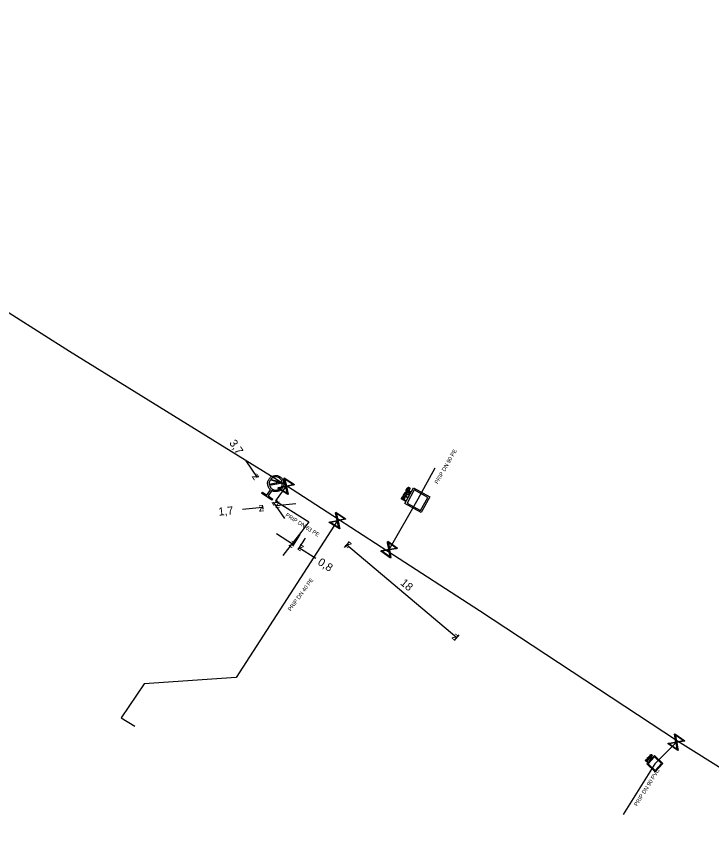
# Model space of a CAD drawing. Extents: x -643544 to -637295, y -1119190 to -1111715.
# Drawn here: x -642792.2 to -642705.4, y -1114896.7 to -1114793.9 of the extents above; entities that cross this region are included whole.
import ezdxf

# ---------------------------------------------------------------- set-up
doc = ezdxf.new("R2010")
doc.units = 0
for name, color, linetype in [('Default', 7, 'Continuous'), ('VP Hydrant', 7, 'Continuous'), ('VP Kótování', 7, 'Continuous'), ('VP Popis přípojky', 7, 'Continuous'), ('VP Přípojka', 7, 'Continuous'), ('VP Řad', 7, 'Continuous'), ('VP Šachta', 7, 'Continuous'), ('VP Šoupě', 7, 'Continuous')]:
    doc.layers.add(name, color=color, linetype=linetype)

msp = doc.modelspace()

# ---------------------------------------------------------------- linework, layer by layer
at = {"layer": 'Default'}
for points in [[(-642760.44, -1114852.98), (-642760.72, -1114852.76), (-642760.78, -1114852.4), (-642760.86, -1114851.99), (-642760.63, -1114851.65), (-642760.39, -1114851.3), (-642759.99, -1114851.23), (-642759.58, -1114851.15), (-642759.24, -1114851.38), (-642758.9, -1114851.62), (-642758.82, -1114852.02), (-642758.74, -1114852.43), (-642758.97, -1114852.77), (-642759.21, -1114853.11), (-642759.61, -1114853.19), (-642759.97, -1114853.26), (-642760.29, -1114853.09)], [(-642759.02, -1114851.97), (-642759.1, -1114851.7), (-642759.34, -1114851.54), (-642759.62, -1114851.35), (-642759.95, -1114851.41), (-642760.28, -1114851.48), (-642760.47, -1114851.76), (-642760.63, -1114851.99), (-642760.61, -1114852.27)], [(-642760.58, -1114852.45), (-642760.5, -1114852.72), (-642760.26, -1114852.88), (-642759.98, -1114853.07), (-642759.65, -1114853.01), (-642759.32, -1114852.95), (-642759.13, -1114852.67), (-642758.96, -1114852.43), (-642758.99, -1114852.15)], [(-642743.76, -1114853.45), (-642743.72, -1114853.39), (-642743.69, -1114853.36), (-642743.66, -1114853.33), (-642743.61, -1114853.33), (-642743.57, -1114853.33), (-642743.52, -1114853.35), (-642743.47, -1114853.38), (-642743.45, -1114853.44), (-642743.44, -1114853.49), (-642743.46, -1114853.57), (-642743.44, -1114853.55), (-642743.42, -1114853.54), (-642743.38, -1114853.53), (-642743.32, -1114853.52)], [(-642743.54, -1114853.59), (-642743.52, -1114853.54), (-642743.51, -1114853.51), (-642743.51, -1114853.48), (-642743.52, -1114853.46), (-642743.54, -1114853.43), (-642743.56, -1114853.42), (-642743.6, -1114853.4), (-642743.63, -1114853.41), (-642743.67, -1114853.43), (-642743.7, -1114853.48)], [(-642743.32, -1114853.6), (-642743.38, -1114853.61), (-642743.42, -1114853.61), (-642743.45, -1114853.62), (-642743.47, -1114853.63), (-642743.49, -1114853.64), (-642743.5, -1114853.65), (-642743.51, -1114853.66), (-642743.52, -1114853.69)], [(-642743.4, -1114852.81), (-642743.38, -1114852.76), (-642743.36, -1114852.74), (-642743.33, -1114852.71), (-642743.3, -1114852.69), (-642743.27, -1114852.67), (-642743.23, -1114852.68), (-642743.19, -1114852.68), (-642743.15, -1114852.7), (-642743.09, -1114852.74), (-642743.07, -1114852.8), (-642743.04, -1114852.86), (-642743.1, -1114852.97)], [(-642743.16, -1114852.94), (-642743.13, -1114852.87), (-642743.13, -1114852.83), (-642743.14, -1114852.79), (-642743.19, -1114852.77), (-642743.22, -1114852.75), (-642743.25, -1114852.76), (-642743.28, -1114852.76), (-642743.3, -1114852.78), (-642743.32, -1114852.79), (-642743.34, -1114852.84)], [(-642744.02, -1114853.94), (-642744, -1114853.89), (-642743.98, -1114853.86), (-642743.95, -1114853.83), (-642743.92, -1114853.81), (-642743.89, -1114853.8), (-642743.85, -1114853.8), (-642743.81, -1114853.8), (-642743.77, -1114853.82), (-642743.71, -1114853.86), (-642743.69, -1114853.92), (-642743.66, -1114853.99), (-642743.72, -1114854.09)], [(-642743.78, -1114854.06), (-642743.75, -1114854), (-642743.76, -1114853.96), (-642743.76, -1114853.92), (-642743.81, -1114853.89), (-642743.84, -1114853.88), (-642743.87, -1114853.88), (-642743.9, -1114853.88), (-642743.92, -1114853.9), (-642743.94, -1114853.92), (-642743.96, -1114853.96)], [(-642713.35, -1114886.44), (-642713.32, -1114886.41), (-642713.3, -1114886.4), (-642713.27, -1114886.39), (-642713.24, -1114886.39), (-642713.22, -1114886.4), (-642713.19, -1114886.42), (-642713.17, -1114886.44), (-642713.16, -1114886.48), (-642713.16, -1114886.51), (-642713.19, -1114886.56), (-642713.17, -1114886.55), (-642713.16, -1114886.55), (-642713.13, -1114886.55), (-642713.1, -1114886.55)], [(-642713.24, -1114886.56), (-642713.22, -1114886.53), (-642713.21, -1114886.52), (-642713.21, -1114886.5), (-642713.21, -1114886.48), (-642713.21, -1114886.47), (-642713.23, -1114886.45), (-642713.25, -1114886.44), (-642713.27, -1114886.44), (-642713.29, -1114886.44), (-642713.32, -1114886.47)], [(-642713.04, -1114886.11), (-642713.01, -1114886.08), (-642713, -1114886.07), (-642712.98, -1114886.06), (-642712.96, -1114886.05), (-642712.93, -1114886.05), (-642712.91, -1114886.05), (-642712.89, -1114886.06), (-642712.87, -1114886.08), (-642712.83, -1114886.11), (-642712.83, -1114886.15), (-642712.83, -1114886.2), (-642712.88, -1114886.25)], [(-642712.91, -1114886.22), (-642712.88, -1114886.19), (-642712.88, -1114886.16), (-642712.88, -1114886.14), (-642712.9, -1114886.12), (-642712.92, -1114886.1), (-642712.94, -1114886.1), (-642712.96, -1114886.1), (-642712.97, -1114886.11), (-642712.98, -1114886.11), (-642713, -1114886.14)], [(-642713.59, -1114886.69), (-642713.56, -1114886.67), (-642713.55, -1114886.66), (-642713.53, -1114886.64), (-642713.51, -1114886.64), (-642713.48, -1114886.63), (-642713.46, -1114886.64), (-642713.44, -1114886.65), (-642713.42, -1114886.66), (-642713.38, -1114886.7), (-642713.38, -1114886.74), (-642713.38, -1114886.78), (-642713.43, -1114886.84)], [(-642713.46, -1114886.81), (-642713.43, -1114886.77), (-642713.43, -1114886.75), (-642713.43, -1114886.72), (-642713.45, -1114886.7), (-642713.47, -1114886.69), (-642713.49, -1114886.68), (-642713.5, -1114886.68), (-642713.52, -1114886.69), (-642713.53, -1114886.7), (-642713.55, -1114886.72)], [(-642713.11, -1114886.6), (-642713.15, -1114886.59), (-642713.17, -1114886.59), (-642713.19, -1114886.59), (-642713.2, -1114886.59), (-642713.22, -1114886.6), (-642713.23, -1114886.6), (-642713.23, -1114886.61), (-642713.25, -1114886.62)]]:
    msp.add_open_spline(points, degree=3, dxfattribs=at)
at = {"layer": 'VP Hydrant'}
for points in [[(-642760.61, -1114852.27), (-642759.02, -1114851.97)], [(-642758.99, -1114852.15), (-642760.58, -1114852.45)], [(-642760.29, -1114853.09), (-642760.75, -1114853.76), (-642760.18, -1114854.15), (-642760.28, -1114854.3), (-642761.57, -1114853.42), (-642761.47, -1114853.27), (-642760.9, -1114853.66), (-642760.44, -1114852.98)]]:
    msp.add_lwpolyline(points, dxfattribs=at)
at = {"layer": 'VP Kótování'}
for points in [[(-642763.54, -1114849.38), (-642762.14, -1114851.45)], [(-642762.31, -1114851.57), (-642762.34, -1114851.59)], [(-642760.24, -1114854.64), (-642760.27, -1114854.66)], [(-642758.67, -1114856.59), (-642760.07, -1114854.52)], [(-642763.94, -1114855.42), (-642761.45, -1114855.17)], [(-642761.47, -1114855.03), (-642761.43, -1114855.42)], [(-642759.78, -1114854.85), (-642759.74, -1114855.24)], [(-642757.28, -1114854.74), (-642759.76, -1114854.99)], [(-642759.69, -1114858.46), (-642757.58, -1114859.81)], [(-642756.8, -1114858.58), (-642757.72, -1114860.02)], [(-642756.12, -1114859.01), (-642757.04, -1114860.45)], [(-642750.7, -1114859.51), (-642751.28, -1114860.19)], [(-642750.96, -1114859.81), (-642737.21, -1114871.42)], [(-642754.8, -1114861.58), (-642756.91, -1114860.24)], [(-642736.95, -1114871.12), (-642737.53, -1114871.81)]]:
    msp.add_lwpolyline(points, dxfattribs=at)
at = {"layer": 'VP Přípojka'}
for points in [[(-642745.8, -1114860.67), (-642745.65, -1114860.46), (-642742.04, -1114854.13), (-642739.89, -1114850.23)], [(-642758.47, -1114852.47), (-642759.83, -1114854.36), (-642755.69, -1114856.99), (-642756.53, -1114858.15), (-642758.9, -1114861.18)], [(-642759.57, -1114851.76), (-642759.63, -1114851.96), (-642759.8, -1114852.21)], [(-642751.97, -1114856.67), (-642752.08, -1114856.84), (-642764.74, -1114876.44), (-642776.24, -1114877.24), (-642779.1, -1114881.47), (-642777.39, -1114882.49)], [(-642709.67, -1114884.33), (-642709.8, -1114884.52), (-642712.49, -1114887.2), (-642716.46, -1114893.56)]]:
    msp.add_lwpolyline(points, dxfattribs=at)
at = {"layer": 'VP Řad'}
msp.add_lwpolyline([(-642849.95, -1114793.87), (-642849.68, -1114794.07), (-642849.36, -1114794.26), (-642849.36, -1114794.26), (-642820.03, -1114813.79), (-642806.82, -1114822.17), (-642785.56, -1114835.66), (-642759.57, -1114851.76), (-642758.47, -1114852.47), (-642751.97, -1114856.67), (-642745.8, -1114860.67), (-642734.36, -1114868.06), (-642709.67, -1114884.33), (-642689.97, -1114896.67)], dxfattribs=at)
at = {"layer": 'VP Šachta'}
for points in [[(-642743.38, -1114853.95), (-642743.88, -1114853.68), (-642743.76, -1114853.45)], [(-642743.7, -1114853.48), (-642743.79, -1114853.64), (-642743.62, -1114853.73)], [(-642742.59, -1114852.74), (-642740.56, -1114853.86), (-642741.65, -1114855.84), (-642743.69, -1114854.72), (-642742.59, -1114852.74)], [(-642743.62, -1114853.73), (-642743.54, -1114853.59)], [(-642743.1, -1114853.44), (-642743.6, -1114853.17), (-642743.56, -1114853.1), (-642743.06, -1114853.38), (-642743.1, -1114853.44)], [(-642743, -1114853.28), (-642743.51, -1114853), (-642743.4, -1114852.81)], [(-642743.42, -1114854.65), (-642741.73, -1114855.58), (-642740.83, -1114853.93), (-642742.52, -1114853), (-642743.42, -1114854.65)], [(-642743.34, -1114852.84), (-642743.41, -1114852.97), (-642743.23, -1114853.07)], [(-642743.32, -1114853.52), (-642743.14, -1114853.51), (-642743.18, -1114853.6), (-642743.32, -1114853.6)], [(-642743.23, -1114853.07), (-642743.16, -1114852.94)], [(-642743.1, -1114852.97), (-642743.17, -1114853.1), (-642742.97, -1114853.21), (-642743, -1114853.28)], [(-642743.63, -1114854.4), (-642744.13, -1114854.12), (-642744.02, -1114853.94)], [(-642743.96, -1114853.96), (-642744.03, -1114854.09), (-642743.85, -1114854.19)], [(-642743.85, -1114854.19), (-642743.78, -1114854.06)], [(-642743.72, -1114854.09), (-642743.79, -1114854.22), (-642743.59, -1114854.34), (-642743.63, -1114854.4)], [(-642743.52, -1114853.69), (-642743.57, -1114853.76), (-642743.34, -1114853.89), (-642743.38, -1114853.95)], [(-642712.54, -1114886.19), (-642711.48, -1114887.18), (-642712.44, -1114888.21), (-642713.5, -1114887.22), (-642712.54, -1114886.19)], [(-642713.2, -1114886.8), (-642713.46, -1114886.56), (-642713.35, -1114886.44)], [(-642713.32, -1114886.47), (-642713.4, -1114886.55), (-642713.31, -1114886.63)], [(-642713.33, -1114887.22), (-642712.45, -1114888.04), (-642711.65, -1114887.19), (-642712.53, -1114886.36), (-642713.33, -1114887.22)], [(-642713.31, -1114886.63), (-642713.24, -1114886.56)], [(-642712.95, -1114886.54), (-642713.21, -1114886.29), (-642713.18, -1114886.26), (-642712.92, -1114886.51), (-642712.95, -1114886.54)], [(-642712.87, -1114886.45), (-642713.13, -1114886.21), (-642713.04, -1114886.11)], [(-642713.1, -1114886.55), (-642712.98, -1114886.57), (-642713.02, -1114886.62), (-642713.11, -1114886.6)], [(-642713, -1114886.14), (-642713.07, -1114886.2), (-642712.97, -1114886.29)], [(-642712.97, -1114886.29), (-642712.91, -1114886.22)], [(-642712.88, -1114886.25), (-642712.94, -1114886.32), (-642712.84, -1114886.42), (-642712.87, -1114886.45)], [(-642713.42, -1114887.04), (-642713.68, -1114886.79), (-642713.59, -1114886.69)], [(-642713.55, -1114886.72), (-642713.62, -1114886.79), (-642713.52, -1114886.88)], [(-642713.52, -1114886.88), (-642713.46, -1114886.81)], [(-642713.43, -1114886.84), (-642713.49, -1114886.9), (-642713.39, -1114887), (-642713.42, -1114887.04)], [(-642713.25, -1114886.62), (-642713.28, -1114886.66), (-642713.17, -1114886.77), (-642713.2, -1114886.8)]]:
    msp.add_lwpolyline(points, dxfattribs=at)
at = {"layer": 'VP Šoupě'}
for points in [[(-642758.74, -1114851.5), (-642757.47, -1114852.31), (-642757.51, -1114852.37), (-642757.64, -1114852.39), (-642758.46, -1114852.57), (-642758.25, -1114853.52), (-642758.28, -1114853.58), (-642759.55, -1114852.77), (-642759.51, -1114852.71), (-642758.56, -1114852.51), (-642758.74, -1114851.69), (-642758.77, -1114851.56), (-642758.74, -1114851.5)], [(-642760.34, -1114851.7), (-642758.9, -1114852.13), (-642758.93, -1114852.22), (-642760.36, -1114851.79), (-642760.34, -1114851.7)], [(-642758.36, -1114853.42), (-642758.54, -1114852.59), (-642759.36, -1114852.77), (-642758.36, -1114853.42)], [(-642758.65, -1114851.67), (-642758.48, -1114852.49), (-642757.66, -1114852.31), (-642758.65, -1114851.67)], [(-642751.86, -1114857.88), (-642753.12, -1114857.06), (-642753.08, -1114857.01), (-642752.96, -1114856.98), (-642752.13, -1114856.81), (-642752.34, -1114855.86), (-642752.3, -1114855.8), (-642751.04, -1114856.62), (-642751.08, -1114856.67), (-642752.03, -1114856.87), (-642751.85, -1114857.7), (-642751.82, -1114857.82), (-642751.86, -1114857.88)], [(-642752.22, -1114855.96), (-642752.05, -1114856.79), (-642751.23, -1114856.61), (-642752.22, -1114855.96)], [(-642751.94, -1114857.71), (-642752.12, -1114856.89), (-642752.93, -1114857.07), (-642751.94, -1114857.71)], [(-642745.83, -1114859.41), (-642744.6, -1114860.29), (-642744.64, -1114860.34), (-642744.77, -1114860.36), (-642745.6, -1114860.5), (-642745.44, -1114861.45), (-642745.47, -1114861.51), (-642746.7, -1114860.64), (-642746.66, -1114860.58), (-642745.7, -1114860.42), (-642745.84, -1114859.6), (-642745.86, -1114859.47), (-642745.83, -1114859.41)], [(-642745.75, -1114859.58), (-642745.61, -1114860.41), (-642744.79, -1114860.27), (-642745.75, -1114859.58)], [(-642745.54, -1114861.34), (-642745.68, -1114860.51), (-642746.51, -1114860.65), (-642745.54, -1114861.34)], [(-642709.61, -1114885.56), (-642710.84, -1114884.71), (-642710.81, -1114884.65), (-642710.68, -1114884.63), (-642709.85, -1114884.48), (-642710.02, -1114883.53), (-642709.99, -1114883.48), (-642708.76, -1114884.33), (-642708.79, -1114884.39), (-642709.75, -1114884.56), (-642709.6, -1114885.38), (-642709.58, -1114885.51), (-642709.61, -1114885.56)], [(-642709.91, -1114883.64), (-642709.77, -1114884.47), (-642708.94, -1114884.32), (-642709.91, -1114883.64)], [(-642709.69, -1114885.4), (-642709.84, -1114884.57), (-642710.66, -1114884.72), (-642709.69, -1114885.4)]]:
    msp.add_lwpolyline(points, dxfattribs=at)

# ---------------------------------------------------------------- texts
at = {"layer": 'VP Kótování'}
for s, rotation, p in [('3,7', 304.0385, (-642765.65, -1114847.14)), ('z', 304.0385, (-642762.83, -1114851.32)), ('z', 124.0385, (-642759.37, -1114854.65)), ('z', 185.8731, (-642759.32, -1114854.44)), ('1,7', 5.8731, (-642766.91, -1114856.23)), ('z', 5.8731, (-642761.9, -1114855.72)), ('z', 327.48, (-642758.27, -1114859.96)), ('z', 147.48, (-642756.22, -1114860.08)), ('z', 139.8081, (-642750.25, -1114859.75)), ('0,8', 327.48, (-642754.65, -1114862.27)), ('18', 319.8081, (-642744.33, -1114864.75)), ('z', 319.8081, (-642737.91, -1114871.48))]:
    msp.add_text(s, height=1, rotation=rotation, dxfattribs=at).set_placement(p)
at = {"layer": 'VP Popis přípojky'}
for s, rotation, p in [('PRIP DN 90 PE', 60.1403, (-642739.59, -1114852.31)), ('PRIP DN 63 PE', 327.5429, (-642758.65, -1114856.26)), ('PRIP DN 40 PE', 54.0583, (-642757.93, -1114868.19)), ('PRIP DN 90 PVC', 58.0222, (-642714.7, -1114892.56))]:
    msp.add_text(s, height=0.5, rotation=rotation, dxfattribs=at).set_placement(p)

doc.saveas('drawing.dxf')
